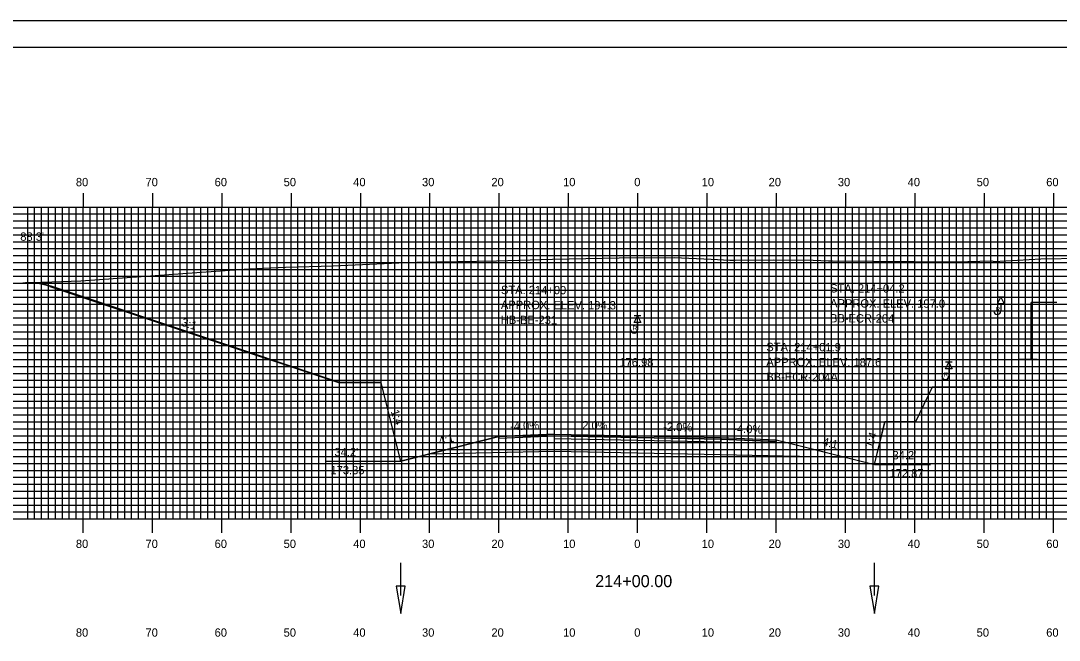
# Model space of a CAD drawing. Extents: x 1795633 to 1795976, y 442591 to 442811.
# Drawn here: x 1795709.9 to 1795859.7, y 442721.2 to 442810.5 of the extents above; entities that cross this region are included whole.
import ezdxf

# ---------------------------------------------------------------- set-up
doc = ezdxf.new("R2010")
doc.units = 0
for name, color, linetype in [('ANNOTATION', 7, 'Continuous'), ('BORDER', 7, 'Continuous'), ('BORING - REFUSAL', 7, 'Continuous'), ('D_Drainage_Ditch_Line', 7, 'Continuous'), ('D_Roadway_Centerline', 7, 'Continuous'), ('D_Roadway_Centerline_Text', 7, 'Continuous'), ('D_Roadway_Edge_Shoulder', 7, 'Continuous'), ('D_Roadway_Edge_TW', 7, 'Continuous'), ('D_Roadway_Pavement', 7, 'Continuous'), ('D_Roadway_SlopeLines', 7, 'Continuous'), ('D_Roadway_SubGrade', 7, 'Continuous'), ('D_Text_Standard', 7, 'Continuous'), ('H_V ANNOTATION', 7, 'Continuous'), ('MAJOR', 7, 'Continuous'), ('MINOR', 7, 'Continuous'), ('PDRAIN', 7, 'Continuous'), ('PLOT BOUNDARY', 7, 'Continuous'), ('S_Roadway_Centerline', 7, 'Continuous')]:
    doc.layers.add(name, color=color, linetype=linetype)

msp = doc.modelspace()

# ---------------------------------------------------------------- linework, layer by layer
at = {"layer": 'ANNOTATION'}
for p, q in [((1795855.68, 442761.67), (1795853.88, 442761.67)), ((1795841.41, 442757.67), (1795838.98, 442752.67)), ((1795853.88, 442757.67), (1795841.41, 442757.67)), ((1795833.05, 442746.54), (1795834.59, 442752.67))]:
    msp.add_line(p, q, dxfattribs=at)
for points in [[(1795855.68, 442761.67), (1795855.68, 442769.87)], [(1795859.36, 442769.87), (1795855.68, 442769.87)], [(1795853.88, 442757.67), (1795853.88, 442761.67)], [(1795838.98, 442752.67), (1795834.58, 442752.67)]]:
    msp.add_lwpolyline(points, dxfattribs=at)
at = {"layer": 'BORDER'}
msp.add_lwpolyline([(1795649.28, 442596.67), (1795969.28, 442596.67), (1795969.28, 442806.67), (1795649.28, 442806.67)], close=True, dxfattribs=at)
at = {"layer": 'BORING - REFUSAL'}
for p, q in [((1795851.76, 442770.67), (1795850.8, 442770.67)), ((1795851.28, 442769.71), (1795851.28, 442768.65)), ((1795799.36, 442767.97), (1795798.4, 442767.97)), ((1795798.88, 442767.01), (1795798.88, 442765.95)), ((1795844.26, 442761.27), (1795843.3, 442761.27)), ((1795843.78, 442760.31), (1795843.78, 442759.25))]:
    msp.add_line(p, q, dxfattribs=at)
for points in [[(1795851.28, 442770.67), (1795851.76, 442769.71), (1795850.8, 442769.71)], [(1795798.88, 442767.97), (1795799.36, 442767.01), (1795798.4, 442767.01)], [(1795843.78, 442761.27), (1795844.26, 442760.31), (1795843.3, 442760.31)]]:
    msp.add_lwpolyline(points, close=True, dxfattribs=at)
for centre in [(1795850.79, 442768.65), (1795798.39, 442765.95), (1795843.29, 442759.25)]:
    msp.add_arc(centre, 0.485, 180, 0, dxfattribs=at)
at = {"layer": 'D_Drainage_Ditch_Line'}
for p, q in [((1795764.71, 442727.63), (1795764.71, 442732.33)), ((1795833.05, 442727.63), (1795833.05, 442732.33))]:
    msp.add_line(p, q, dxfattribs=at)
for points in [[(1795765.36, 442728.94), (1795764.05, 442728.94), (1795764.71, 442725)], [(1795833.71, 442728.94), (1795832.4, 442728.94), (1795833.05, 442725)]]:
    msp.add_lwpolyline(points, close=True, dxfattribs=at)
at = {"layer": 'D_Roadway_Centerline'}
msp.add_lwpolyline([(1795764.71, 442747.02), (1795768.71, 442748.02), (1795778.88, 442750.56), (1795786.88, 442750.88), (1795798.88, 442750.64), (1795810.88, 442750.4), (1795818.88, 442750.08), (1795829.05, 442747.54), (1795833.05, 442746.54), (1795834.58, 442752.66)], dxfattribs=at)
at = {"layer": 'D_Roadway_Edge_Shoulder'}
for points in [[(1795786.88, 442750.88), (1795778.88, 442750.56), (1795778.88, 442750.31), (1795786.88, 442750.63)], [(1795810.88, 442750.4), (1795818.88, 442750.08), (1795818.88, 442749.83), (1795810.88, 442750.15)]]:
    msp.add_lwpolyline(points, close=True, dxfattribs=at)
at = {"layer": 'D_Roadway_Edge_TW'}
msp.add_lwpolyline([(1795786.88, 442750.63), (1795786.88, 442750.88), (1795798.88, 442750.64), (1795810.88, 442750.4), (1795810.88, 442750.15), (1795798.88, 442750.39)], close=True, dxfattribs=at)
at = {"layer": 'D_Roadway_Pavement'}
msp.add_lwpolyline([(1795786.88, 442750.22), (1795786.88, 442750.63), (1795798.88, 442750.39), (1795810.88, 442750.15), (1795810.88, 442749.74), (1795798.88, 442749.98)], close=True, dxfattribs=at)
at = {"layer": 'D_Roadway_SlopeLines'}
for p, q in [((1795714.08, 442772.22), (1795755.89, 442758.28)), ((1795761.89, 442758.28), (1795755.89, 442758.28)), ((1795764.71, 442747.02), (1795761.89, 442758.28))]:
    msp.add_line(p, q, dxfattribs=at)
for points in [[(1795761.89, 442758.28), (1795761.87, 442758.37), (1795755.87, 442758.37), (1795714.28, 442772.23)], [(1795778.88, 442750.56), (1795764.71, 442747.02)], [(1795818.88, 442750.08), (1795833.05, 442746.54)]]:
    msp.add_lwpolyline(points, dxfattribs=at)
for centre in [(1795710.85, 442762.54), (1795711.05, 442762.55)]:
    msp.add_arc(centre, 10.2, 71.5651, 91.5576, dxfattribs=at)
at = {"layer": 'D_Roadway_SubGrade'}
msp.add_lwpolyline([(1795786.88, 442748.38), (1795768.71, 442748.02), (1795778.88, 442750.56), (1795778.88, 442750.31), (1795786.88, 442750.63), (1795798.88, 442750.39), (1795810.88, 442750.15), (1795818.88, 442749.83), (1795818.88, 442750.08), (1795829.05, 442747.54), (1795810.88, 442747.9), (1795798.88, 442748.14)], close=True, dxfattribs=at)
at = {"layer": 'MAJOR'}
for p, q in [((1795718.88, 442785.67), (1795718.88, 442783.67)), ((1795728.88, 442785.67), (1795728.88, 442783.67)), ((1795738.88, 442785.67), (1795738.88, 442783.67)), ((1795748.88, 442785.67), (1795748.88, 442783.67)), ((1795758.88, 442785.67), (1795758.88, 442783.67)), ((1795768.88, 442785.67), (1795768.88, 442783.67)), ((1795778.88, 442785.67), (1795778.88, 442783.67)), ((1795788.88, 442785.67), (1795788.88, 442783.67)), ((1795798.88, 442785.67), (1795798.88, 442783.67)), ((1795808.88, 442785.67), (1795808.88, 442783.67)), ((1795818.88, 442785.67), (1795818.88, 442783.67)), ((1795828.88, 442785.67), (1795828.88, 442783.67)), ((1795838.88, 442785.67), (1795838.88, 442783.67)), ((1795848.88, 442785.67), (1795848.88, 442783.67)), ((1795858.88, 442785.67), (1795858.88, 442783.67)), ((1795658.88, 442783.67), (1795938.88, 442783.67)), ((1795658.88, 442783.67), (1795938.88, 442783.67)), ((1795718.88, 442738.67), (1795718.88, 442783.67)), ((1795728.88, 442738.67), (1795728.88, 442783.67)), ((1795738.88, 442738.67), (1795738.88, 442783.67)), ((1795748.88, 442738.67), (1795748.88, 442783.67)), ((1795758.88, 442738.67), (1795758.88, 442783.67)), ((1795768.88, 442738.67), (1795768.88, 442783.67)), ((1795778.88, 442738.67), (1795778.88, 442783.67)), ((1795788.88, 442738.67), (1795788.88, 442783.67)), ((1795798.88, 442738.67), (1795798.88, 442783.67)), ((1795808.88, 442738.67), (1795808.88, 442783.67)), ((1795818.88, 442738.67), (1795818.88, 442783.67)), ((1795828.88, 442738.67), (1795828.88, 442783.67)), ((1795838.88, 442738.67), (1795838.88, 442783.67)), ((1795848.88, 442738.67), (1795848.88, 442783.67)), ((1795858.88, 442738.67), (1795858.88, 442783.67)), ((1795658.88, 442778.67), (1795938.88, 442778.67)), ((1795658.88, 442773.67), (1795938.88, 442773.67)), ((1795658.88, 442768.67), (1795938.88, 442768.67)), ((1795658.88, 442763.67), (1795938.88, 442763.67)), ((1795658.88, 442758.67), (1795938.88, 442758.67)), ((1795658.88, 442753.67), (1795938.88, 442753.67)), ((1795658.88, 442748.67), (1795938.88, 442748.67)), ((1795658.88, 442743.67), (1795938.88, 442743.67)), ((1795658.88, 442738.67), (1795938.88, 442738.67)), ((1795658.88, 442738.67), (1795938.88, 442738.67)), ((1795718.88, 442736.66), (1795718.88, 442738.67)), ((1795728.88, 442736.66), (1795728.88, 442738.67)), ((1795738.88, 442736.66), (1795738.88, 442738.67)), ((1795748.88, 442736.66), (1795748.88, 442738.67)), ((1795758.88, 442736.66), (1795758.88, 442738.67)), ((1795768.88, 442736.66), (1795768.88, 442738.67)), ((1795778.88, 442736.66), (1795778.88, 442738.67)), ((1795788.88, 442736.66), (1795788.88, 442738.67)), ((1795798.88, 442736.66), (1795798.88, 442738.67)), ((1795808.88, 442736.66), (1795808.88, 442738.67)), ((1795818.88, 442736.66), (1795818.88, 442738.67)), ((1795828.88, 442736.66), (1795828.88, 442738.67)), ((1795838.88, 442736.66), (1795838.88, 442738.67)), ((1795848.88, 442736.66), (1795848.88, 442738.67)), ((1795858.88, 442736.66), (1795858.88, 442738.67))]:
    msp.add_line(p, q, dxfattribs=at)
at = {"layer": 'MINOR'}
for p, q in [((1795710.88, 442738.67), (1795710.88, 442783.67)), ((1795711.88, 442738.67), (1795711.88, 442783.67)), ((1795712.88, 442738.67), (1795712.88, 442783.67)), ((1795713.88, 442738.67), (1795713.88, 442783.67)), ((1795714.88, 442738.67), (1795714.88, 442783.67)), ((1795715.88, 442738.67), (1795715.88, 442783.67)), ((1795716.88, 442738.67), (1795716.88, 442783.67)), ((1795717.88, 442738.67), (1795717.88, 442783.67)), ((1795719.88, 442738.67), (1795719.88, 442783.67)), ((1795720.88, 442738.67), (1795720.88, 442783.67)), ((1795721.88, 442738.67), (1795721.88, 442783.67)), ((1795722.88, 442738.67), (1795722.88, 442783.67)), ((1795723.88, 442738.67), (1795723.88, 442783.67)), ((1795724.88, 442738.67), (1795724.88, 442783.67)), ((1795725.88, 442738.67), (1795725.88, 442783.67)), ((1795726.88, 442738.67), (1795726.88, 442783.67)), ((1795727.88, 442738.67), (1795727.88, 442783.67)), ((1795729.88, 442738.67), (1795729.88, 442783.67)), ((1795730.88, 442738.67), (1795730.88, 442783.67)), ((1795731.88, 442738.67), (1795731.88, 442783.67)), ((1795732.88, 442738.67), (1795732.88, 442783.67)), ((1795733.88, 442738.67), (1795733.88, 442783.67)), ((1795734.88, 442738.67), (1795734.88, 442783.67)), ((1795735.88, 442738.67), (1795735.88, 442783.67)), ((1795736.88, 442738.67), (1795736.88, 442783.67)), ((1795737.88, 442738.67), (1795737.88, 442783.67)), ((1795739.88, 442738.67), (1795739.88, 442783.67)), ((1795740.88, 442738.67), (1795740.88, 442783.67)), ((1795741.88, 442738.67), (1795741.88, 442783.67)), ((1795742.88, 442738.67), (1795742.88, 442783.67)), ((1795743.88, 442738.67), (1795743.88, 442783.67)), ((1795744.88, 442738.67), (1795744.88, 442783.67)), ((1795745.88, 442738.67), (1795745.88, 442783.67)), ((1795746.88, 442738.67), (1795746.88, 442783.67)), ((1795747.88, 442738.67), (1795747.88, 442783.67)), ((1795749.88, 442738.67), (1795749.88, 442783.67)), ((1795750.88, 442738.67), (1795750.88, 442783.67)), ((1795751.88, 442738.67), (1795751.88, 442783.67)), ((1795752.88, 442738.67), (1795752.88, 442783.67)), ((1795753.88, 442738.67), (1795753.88, 442783.67)), ((1795754.88, 442738.67), (1795754.88, 442783.67)), ((1795755.88, 442738.67), (1795755.88, 442783.67)), ((1795756.88, 442738.67), (1795756.88, 442783.67)), ((1795757.88, 442738.67), (1795757.88, 442783.67)), ((1795759.88, 442738.67), (1795759.88, 442783.67)), ((1795760.88, 442738.67), (1795760.88, 442783.67)), ((1795761.88, 442738.67), (1795761.88, 442783.67)), ((1795762.88, 442738.67), (1795762.88, 442783.67)), ((1795763.88, 442738.67), (1795763.88, 442783.67)), ((1795764.88, 442738.67), (1795764.88, 442783.67)), ((1795765.88, 442738.67), (1795765.88, 442783.67)), ((1795766.88, 442738.67), (1795766.88, 442783.67)), ((1795767.88, 442738.67), (1795767.88, 442783.67)), ((1795769.88, 442738.67), (1795769.88, 442783.67)), ((1795770.88, 442738.67), (1795770.88, 442783.67)), ((1795771.88, 442738.67), (1795771.88, 442783.67)), ((1795772.88, 442738.67), (1795772.88, 442783.67)), ((1795773.88, 442738.67), (1795773.88, 442783.67)), ((1795774.88, 442738.67), (1795774.88, 442783.67)), ((1795775.88, 442738.67), (1795775.88, 442783.67)), ((1795776.88, 442738.67), (1795776.88, 442783.67)), ((1795777.88, 442738.67), (1795777.88, 442783.67)), ((1795779.88, 442738.67), (1795779.88, 442783.67)), ((1795780.88, 442738.67), (1795780.88, 442783.67)), ((1795781.88, 442738.67), (1795781.88, 442783.67)), ((1795782.88, 442738.67), (1795782.88, 442783.67)), ((1795783.88, 442738.67), (1795783.88, 442783.67)), ((1795784.88, 442738.67), (1795784.88, 442783.67)), ((1795785.88, 442738.67), (1795785.88, 442783.67)), ((1795786.88, 442738.67), (1795786.88, 442783.67)), ((1795787.88, 442738.67), (1795787.88, 442783.67)), ((1795789.88, 442738.67), (1795789.88, 442783.67)), ((1795790.88, 442738.67), (1795790.88, 442783.67)), ((1795791.88, 442738.67), (1795791.88, 442783.67)), ((1795792.88, 442738.67), (1795792.88, 442783.67)), ((1795793.88, 442738.67), (1795793.88, 442783.67)), ((1795794.88, 442738.67), (1795794.88, 442783.67)), ((1795795.88, 442738.67), (1795795.88, 442783.67)), ((1795796.88, 442738.67), (1795796.88, 442783.67)), ((1795797.88, 442738.67), (1795797.88, 442783.67)), ((1795799.88, 442738.67), (1795799.88, 442783.67)), ((1795800.88, 442738.67), (1795800.88, 442783.67)), ((1795801.88, 442738.67), (1795801.88, 442783.67)), ((1795802.88, 442738.67), (1795802.88, 442783.67)), ((1795803.88, 442738.67), (1795803.88, 442783.67)), ((1795804.88, 442738.67), (1795804.88, 442783.67)), ((1795805.88, 442738.67), (1795805.88, 442783.67)), ((1795806.88, 442738.67), (1795806.88, 442783.67)), ((1795807.88, 442738.67), (1795807.88, 442783.67)), ((1795809.88, 442738.67), (1795809.88, 442783.67)), ((1795810.88, 442738.67), (1795810.88, 442783.67)), ((1795811.88, 442738.67), (1795811.88, 442783.67)), ((1795812.88, 442738.67), (1795812.88, 442783.67)), ((1795813.88, 442738.67), (1795813.88, 442783.67)), ((1795814.88, 442738.67), (1795814.88, 442783.67)), ((1795815.88, 442738.67), (1795815.88, 442783.67)), ((1795816.88, 442738.67), (1795816.88, 442783.67)), ((1795817.88, 442738.67), (1795817.88, 442783.67)), ((1795819.88, 442738.67), (1795819.88, 442783.67)), ((1795820.88, 442738.67), (1795820.88, 442783.67)), ((1795821.88, 442738.67), (1795821.88, 442783.67)), ((1795822.88, 442738.67), (1795822.88, 442783.67)), ((1795823.88, 442738.67), (1795823.88, 442783.67)), ((1795824.88, 442738.67), (1795824.88, 442783.67)), ((1795825.88, 442738.67), (1795825.88, 442783.67)), ((1795826.88, 442738.67), (1795826.88, 442783.67)), ((1795827.88, 442738.67), (1795827.88, 442783.67)), ((1795829.88, 442738.67), (1795829.88, 442783.67)), ((1795830.88, 442738.67), (1795830.88, 442783.67)), ((1795831.88, 442738.67), (1795831.88, 442783.67)), ((1795832.88, 442738.67), (1795832.88, 442783.67)), ((1795833.88, 442738.67), (1795833.88, 442783.67)), ((1795834.88, 442738.67), (1795834.88, 442783.67)), ((1795835.88, 442738.67), (1795835.88, 442783.67)), ((1795836.88, 442738.67), (1795836.88, 442783.67)), ((1795837.88, 442738.67), (1795837.88, 442783.67)), ((1795839.88, 442738.67), (1795839.88, 442783.67)), ((1795840.88, 442738.67), (1795840.88, 442783.67)), ((1795841.88, 442738.67), (1795841.88, 442783.67)), ((1795842.88, 442738.67), (1795842.88, 442783.67)), ((1795843.88, 442738.67), (1795843.88, 442783.67)), ((1795844.88, 442738.67), (1795844.88, 442783.67)), ((1795845.88, 442738.67), (1795845.88, 442783.67)), ((1795846.88, 442738.67), (1795846.88, 442783.67)), ((1795847.88, 442738.67), (1795847.88, 442783.67)), ((1795849.88, 442738.67), (1795849.88, 442783.67)), ((1795850.88, 442738.67), (1795850.88, 442783.67)), ((1795851.88, 442738.67), (1795851.88, 442783.67)), ((1795852.88, 442738.67), (1795852.88, 442783.67)), ((1795853.88, 442738.67), (1795853.88, 442783.67)), ((1795854.88, 442738.67), (1795854.88, 442783.67)), ((1795855.88, 442738.67), (1795855.88, 442783.67)), ((1795856.88, 442738.67), (1795856.88, 442783.67)), ((1795857.88, 442738.67), (1795857.88, 442783.67)), ((1795658.88, 442782.67), (1795938.88, 442782.67)), ((1795658.88, 442781.67), (1795938.88, 442781.67)), ((1795658.88, 442780.67), (1795938.88, 442780.67)), ((1795658.88, 442779.67), (1795938.88, 442779.67)), ((1795658.88, 442777.67), (1795938.88, 442777.67)), ((1795658.88, 442776.67), (1795938.88, 442776.67)), ((1795658.88, 442775.67), (1795938.88, 442775.67)), ((1795658.88, 442774.67), (1795938.88, 442774.67)), ((1795658.88, 442772.67), (1795938.88, 442772.67)), ((1795658.88, 442771.67), (1795938.88, 442771.67)), ((1795658.88, 442770.67), (1795938.88, 442770.67)), ((1795658.88, 442769.67), (1795938.88, 442769.67)), ((1795658.88, 442767.67), (1795938.88, 442767.67)), ((1795658.88, 442766.67), (1795938.88, 442766.67)), ((1795658.88, 442765.67), (1795938.88, 442765.67)), ((1795658.88, 442764.67), (1795938.88, 442764.67)), ((1795658.88, 442762.67), (1795938.88, 442762.67)), ((1795658.88, 442761.67), (1795938.88, 442761.67)), ((1795658.88, 442760.67), (1795938.88, 442760.67)), ((1795856.55, 442761.67), (1795854.55, 442761.67)), ((1795658.88, 442759.67), (1795938.88, 442759.67)), ((1795658.88, 442757.67), (1795938.88, 442757.67)), ((1795658.88, 442756.67), (1795938.88, 442756.67)), ((1795658.88, 442755.67), (1795938.88, 442755.67)), ((1795658.88, 442754.67), (1795938.88, 442754.67)), ((1795658.88, 442752.67), (1795834.58, 442752.67)), ((1795658.88, 442751.67), (1795938.88, 442751.67)), ((1795834.58, 442752.67), (1795938.88, 442752.67)), ((1795658.88, 442750.67), (1795938.88, 442750.67)), ((1795658.88, 442749.67), (1795938.88, 442749.67)), ((1795658.88, 442747.67), (1795938.88, 442747.67)), ((1795658.88, 442746.67), (1795938.88, 442746.67)), ((1795658.88, 442745.67), (1795938.88, 442745.67)), ((1795658.88, 442744.67), (1795938.88, 442744.67)), ((1795658.88, 442742.67), (1795938.88, 442742.67)), ((1795658.88, 442741.67), (1795938.88, 442741.67)), ((1795658.88, 442740.67), (1795938.88, 442740.67)), ((1795658.88, 442739.67), (1795938.88, 442739.67))]:
    msp.add_line(p, q, dxfattribs=at)
at = {"layer": 'PDRAIN'}
for p, q in [((1795753.98, 442747.02), (1795764.71, 442747.02)), ((1795833.05, 442746.54), (1795841.13, 442746.54))]:
    msp.add_line(p, q, dxfattribs=at)
at = {"layer": 'PLOT BOUNDARY'}
msp.add_lwpolyline([(1795633.09, 442590.55), (1795973.09, 442590.55), (1795973.09, 442810.55), (1795633.09, 442810.55)], close=True, dxfattribs=at)
at = {"layer": 'S_Roadway_Centerline'}
msp.add_lwpolyline([(1795708.79, 442772.67), (1795718.56, 442773.04), (1795735.29, 442774.21), (1795742.81, 442774.75), (1795748.06, 442774.98), (1795754.96, 442775.17), (1795764.42, 442775.61), (1795767.1, 442775.69), (1795778.53, 442775.91), (1795786.63, 442776.15), (1795796.23, 442776.34), (1795804.17, 442776.37), (1795809.5, 442776.14), (1795812.18, 442776.01), (1795812.96, 442776.02), (1795818.49, 442776.05), (1795824.2, 442775.99), (1795826.43, 442775.91), (1795827.01, 442775.89), (1795844.79, 442775.75), (1795849.98, 442775.9), (1795850.35, 442775.8), (1795857.06, 442776.18), (1795862.97, 442776.3)], dxfattribs=at)

# ---------------------------------------------------------------- texts
at = {"layer": 'ANNOTATION'}
for s, rotation, p in [('3:1', 341.5651, (1795732.96, 442766.57)), ('3:1', 341.5651, (1795732.96, 442766.57)), ('1:4', 289.484, (1795763.24, 442754.19)), ('-4.0%', 2.2906, (1795780.51, 442751.43)), ('2.0%', 358.8542, (1795790.89, 442751.6)), ('-2.0%', 358.8542, (1795802.57, 442751.37)), ('-4.0%', 357.7094, (1795812.67, 442751.13)), ('4:1', 14.0362, (1795770.33, 442749.29)), ('4:1', 345.9638, (1795825.47, 442749.3)), ('1:4', 70.516, (1795832.75, 442748.8))]:
    msp.add_text(s, height=1.2, rotation=rotation, dxfattribs=at).set_placement(p)
for s, p in [("34.2'", (1795755.14, 442747.71)), ("34.2'", (1795835.67, 442747.26)), ('173.35', (1795754.57, 442745.11)), ('172.87', (1795835.23, 442744.66))]:
    msp.add_text(s, height=1.2, dxfattribs=at).set_placement(p)
at = {"layer": 'BORING - REFUSAL'}
for s, p in [('STA. 214+00', (1795779.17, 442771.11)), ('STA. 214+04.2', (1795826.67, 442771.34)), ('APPROX. ELEV. 194.3', (1795779.16, 442768.95)), ('APPROX. ELEV. 197.0', (1795826.66, 442769.18)), ('HB-BE-231', (1795779.15, 442766.79)), ('BB-ECR-204', (1795826.65, 442767.02)), ('STA. 214+01.9', (1795817.46, 442762.88)), ('APPROX. ELEV. 187.6', (1795817.46, 442760.72)), ('BB-ECR-204A', (1795817.45, 442758.56))]:
    msp.add_text(s, height=1.2, rotation=359.8142, dxfattribs=at).set_placement(p)
for p in [(1795850.57, 442768.59), (1795798.17, 442765.89), (1795843.07, 442759.19)]:
    msp.add_text('R', height=0.64, dxfattribs=at).set_placement(p)
at = {"layer": 'D_Roadway_Centerline'}
for s, p in [('C', (1795798.87, 442750.64)), ('L', (1795798.88, 442750.63))]:
    msp.add_text(s, height=0.0146, dxfattribs=at).set_placement(p)
at = {"layer": 'D_Roadway_Centerline_Text'}
msp.add_text('176.98', height=1.2, dxfattribs=at).set_placement((1795796.26, 442760.67))
at = {"layer": 'D_Text_Standard'}
msp.add_text("88.3'", height=1.2, dxfattribs=at).set_placement((1795709.81, 442778.8))
at = {"layer": 'H_V ANNOTATION'}
for s, height, p in [('80', 1.2, (1795717.83, 442786.67)), ('70', 1.2, (1795727.88, 442786.67)), ('60', 1.2, (1795737.85, 442786.67)), ('50', 1.2, (1795747.81, 442786.67)), ('40', 1.2, (1795757.85, 442786.67)), ('30', 1.2, (1795767.78, 442786.67)), ('20', 1.2, (1795777.79, 442786.67)), ('10', 1.2, (1795788.13, 442786.67)), ('0', 1.2, (1795798.4, 442786.67)), ('10', 1.2, (1795808.13, 442786.67)), ('20', 1.2, (1795817.79, 442786.67)), ('30', 1.2, (1795827.78, 442786.67)), ('40', 1.2, (1795837.85, 442786.67)), ('50', 1.2, (1795847.81, 442786.67)), ('60', 1.2, (1795857.85, 442786.67)), ('80', 1.2, (1795717.83, 442734.47)), ('70', 1.2, (1795727.88, 442734.47)), ('60', 1.2, (1795737.85, 442734.47)), ('50', 1.2, (1795747.81, 442734.47)), ('40', 1.2, (1795757.85, 442734.47)), ('30', 1.2, (1795767.78, 442734.47)), ('20', 1.2, (1795777.79, 442734.47)), ('10', 1.2, (1795788.13, 442734.47)), ('0', 1.2, (1795798.4, 442734.47)), ('10', 1.2, (1795808.13, 442734.47)), ('20', 1.2, (1795817.79, 442734.47)), ('30', 1.2, (1795827.78, 442734.47)), ('40', 1.2, (1795837.85, 442734.47)), ('50', 1.2, (1795847.81, 442734.47)), ('60', 1.2, (1795857.85, 442734.47)), ('214+00.00', 1.75, (1795792.76, 442728.82)), ('80', 1.2, (1795717.83, 442721.67)), ('70', 1.2, (1795727.88, 442721.67)), ('60', 1.2, (1795737.85, 442721.67)), ('50', 1.2, (1795747.81, 442721.67)), ('40', 1.2, (1795757.85, 442721.67)), ('30', 1.2, (1795767.78, 442721.67)), ('20', 1.2, (1795777.79, 442721.67)), ('10', 1.2, (1795788.13, 442721.67)), ('0', 1.2, (1795798.4, 442721.67)), ('10', 1.2, (1795808.13, 442721.67)), ('20', 1.2, (1795817.79, 442721.67)), ('30', 1.2, (1795827.78, 442721.67)), ('40', 1.2, (1795837.85, 442721.67)), ('50', 1.2, (1795847.81, 442721.67)), ('60', 1.2, (1795857.85, 442721.67))]:
    msp.add_text(s, height=height, dxfattribs=at).set_placement(p)

doc.saveas('drawing.dxf')
